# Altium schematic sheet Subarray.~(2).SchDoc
size A3; SheetNumber: 2; SheetTotal: 4; PageSetup: Record=PageOptions¦CenterHorizontal=True¦CenterVertical=True¦PrintScale=1.01¦XCorrection=1.00¦YCorrection=1.00¦PrintKind=1¦BorderSize=5000000¦LeftOffset=0¦BottomOffset=0¦Orientation=2¦PaperLength=1000¦PaperWidth=1000¦Scale=100¦PaperSource=7¦PrintQuality=600¦MediaType=1¦DitherType=10¦PaperKind=A3¦PrintScaleMode=1
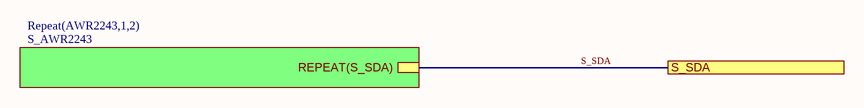
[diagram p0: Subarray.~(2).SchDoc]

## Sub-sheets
Repeat(AWR2243,1,2) = S_AWR2243: REPEAT(S_SDA)

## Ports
S_SDA

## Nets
S_SDA: port S_SDA, sheet Repeat(AWR2243,1,2)/REPEAT(S_SDA)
